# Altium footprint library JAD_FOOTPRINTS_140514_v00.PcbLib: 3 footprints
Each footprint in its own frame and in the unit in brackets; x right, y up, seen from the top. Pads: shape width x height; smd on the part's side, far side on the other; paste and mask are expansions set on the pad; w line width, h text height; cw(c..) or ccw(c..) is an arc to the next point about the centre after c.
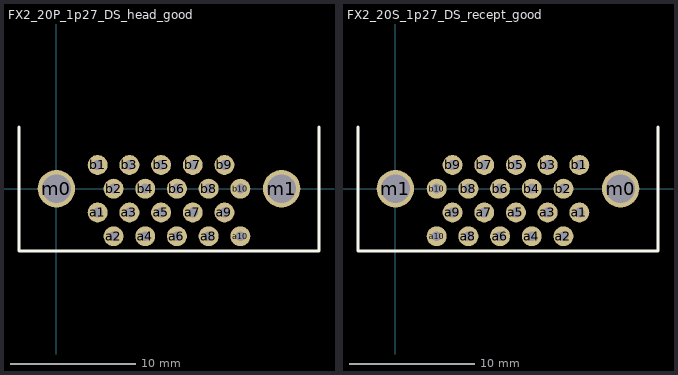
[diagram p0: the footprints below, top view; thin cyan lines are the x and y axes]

## FX2_20P_1p27_DS_head_good [mm] "Hirose FX2-20P-1.27DS: CONN HEADER Right Angle 20POS 1.27MM."
pads (22):
  round 1.6 hole 0.8: a1(3.31,-1.905) a2(4.58,-3.81) a3(5.85,-1.905) a4(7.12,-3.81) a5(8.39,-1.905) a6(9.66,-3.81) a7(10.93,-1.905) a8(12.2,-3.81) a9(13.47,-1.905) a10(14.74,-3.81) b1(3.31,1.905) b2(4.58,0) b3(5.85,1.905) b4(7.12,0) b5(8.39,1.905) b6(9.66,0) b7(10.93,1.905) b8(12.2,0) b9(13.47,1.905) b10(14.74,0)
  round 3 hole 2.3: m0(0,0) m1(18.05,0)
Top Overlay:
  lines w0.254: -3,4.955 -3,-5 21.05,-5 21.05,4.955
M5 Assembly Top:
  text ".Designator" at -2.711,-7.828 h1.02
3D body: height 7.7, standoff -3.1, extent -2.35,-4.595 20.4,10.405

## FX2_20P_1p27_DS_head_try_a [mm] "Hirose FX2-20P-1.27DS: CONN HEADER Right Angle 20POS 1.27MM."
via 3.31,-1.905 diameter 1.27 hole 0.8
via 5.85,-1.905 diameter 1.27 hole 0.8
via 8.39,-1.905 diameter 1.27 hole 0.8
via 10.93,-1.905 diameter 1.27 hole 0.8
via 13.47,-1.905 diameter 1.27 hole 0.8
via 4.58,-3.81 diameter 1.27 hole 0.8
via 7.12,-3.81 diameter 1.27 hole 0.8
via 9.66,-3.81 diameter 1.27 hole 0.8
via 12.2,-3.81 diameter 1.27 hole 0.8
via 14.74,-3.81 diameter 1.27 hole 0.8
via 4.58,0 diameter 1.27 hole 0.8
via 7.12,0 diameter 1.27 hole 0.8
via 9.66,0 diameter 1.27 hole 0.8
via 12.2,0 diameter 1.27 hole 0.8
via 14.74,0 diameter 1.27 hole 0.8
via 13.47,1.905 diameter 1.27 hole 0.8
via 10.93,1.905 diameter 1.27 hole 0.8
via 8.39,1.905 diameter 1.27 hole 0.8
via 5.85,1.905 diameter 1.27 hole 0.8
via 3.31,1.905 diameter 1.27 hole 0.8
via 0,0 diameter 2.8 hole 2.3
via 18.05,0 diameter 2.8 hole 2.3
M5 Assembly Top:
  text ".Designator" at -1.016,-8.128 h1.02

## FX2_20S_1p27_DS_recept_good [mm] "Hirose FX2-20P-1.27DS: CONN receptacle Right Angle 20POS 1.27MM."
pads (22):
  round 1.6 hole 0.8: a1(14.74,-1.905) a2(13.47,-3.81) a3(12.2,-1.905) a4(10.93,-3.81) a5(9.66,-1.905) a6(8.39,-3.81) a7(7.12,-1.905) a8(5.85,-3.81) a9(4.58,-1.905) a10(3.31,-3.81) b1(14.74,1.905) b2(13.47,0) b3(12.2,1.905) b4(10.93,0) b5(9.66,1.905) b6(8.39,0) b7(7.12,1.905) b8(5.85,0) b9(4.58,1.905) b10(3.31,0)
  round 3 hole 2.3: m0(18.05,0) m1(0,0)
Top Overlay:
  lines w0.254: -3,4.955 -3,-5 21.05,-5 21.05,4.955
M5 Assembly Top:
  text ".Designator" at -3.351,-7.248 h1.02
